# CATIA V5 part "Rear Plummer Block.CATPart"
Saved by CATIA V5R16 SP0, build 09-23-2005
Part number: Rear Plummer Block
Bounding box of the stored display mesh (mm): x -23.993 to 23.993, y -2.75 to 2.75, z -23.997 to 23.997
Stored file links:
  C:\V5_education\CATIA Data\ASD\Power Transmission Gear Assembly\Assembly Data\Rear Plummer Block.CATPart
  C:\V5_education\CATIA Data\ASD\Power Transmission Gear Assembly\Assembly Data\Power Transmission Gear Assembly.CATProduct
  C:\V5_education\CATIA Data\ASD\Power Transmission Gear Assembly\Assembly Data\Power Transmission Gear.CATPart
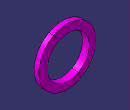
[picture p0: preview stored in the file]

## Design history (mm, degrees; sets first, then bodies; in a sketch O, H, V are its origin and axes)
Set1
  DatumSurface1: linked copy from another document
Set2 "Reference Data"
  Point1 "Center Point": (0, 0, 0)
Body1 (main body)
  Sketch1 on yz-plane, origin (0, 0, 0), H (0, 1, 0), V (0, 0, 1)
    axis line L1 (0, 0) -> (70.7713, 0)
    construction line L2 (0, 0) -> (0, 56.3698)
    point P3 (-2.75, 17.5)
    line L3 (-2.75, 17.5) -> (2.75, 17.5)
    point P4 (2.75, 17.5)
    line L4 (2.75, 17.5) -> (2, 24)
    point P5 (2, 24)
    line L5 (2, 24) -> (-2, 24)
    point P6 (-2, 24)
    line L6 (-2, 24) -> (-2.75, 17.5)
    distance L3 H = 17.5
    distance L5 H = 24
    distance P3 P4 = 5.5
    distance P6 P5 = 4
    horizontal: L1 H, L3 H, L5 H
    vertical: L2 V
    symmetry: L6 L4 L2
  Shaft1: profile Sketch1, axis Sketch1.L1, angle 360
  AssyPrtSPLIT1: SplitPlane DatumSurface1, _MechModInactiveResultOUT result of AssyPrtSPLIT1, deactivated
